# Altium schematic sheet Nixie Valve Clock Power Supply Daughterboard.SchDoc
size A4; SheetNumber: 1; SheetTotal: 3
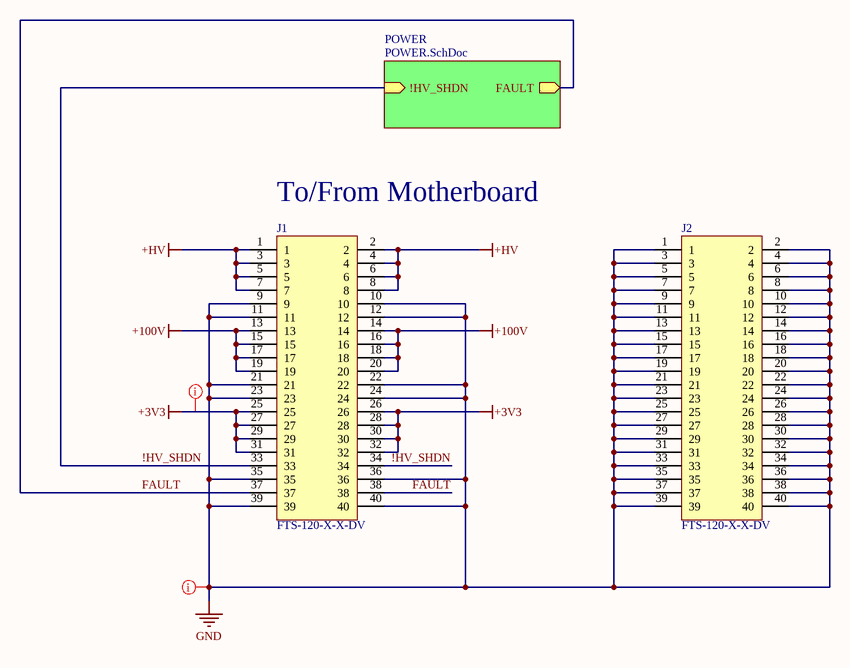
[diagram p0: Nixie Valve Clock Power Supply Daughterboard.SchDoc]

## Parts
?  (no value)
J1  FTS-120-X-X-DV  [SAMTEC_FTS-120-X-X-DV]
J2  FTS-120-X-X-DV  [SAMTEC_FTS-120-X-X-DV]

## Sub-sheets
POWER = POWER.SchDoc: !HV_SHDN (in), FAULT (out)

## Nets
+3V3: J1.25 J1.26 J1.27 J1.28 J1.29 J1.30 J1.31 J1.32
+100V: J1.13 J1.14 J1.15 J1.16 J1.17 J1.18 J1.19 J1.20
+HV: J1.1 J1.2 J1.3 J1.4 J1.5 J1.6 J1.7 J1.8
GND: J1.9 J1.10 J1.11 J1.12 J1.21 J1.22 J1.23 J1.24 J1.35 J1.36 J1.39 J1.40 J2.1 J2.2 J2.3 J2.4 J2.5 J2.6 J2.7 J2.8 J2.9 J2.10 J2.11 J2.12 J2.13 J2.14 J2.15 J2.16 J2.17 J2.18 J2.19 J2.20 J2.21 J2.22 J2.23 J2.24 J2.25 J2.26 J2.27 J2.28 J2.29 J2.30 J2.31 J2.32 J2.33 J2.34 J2.35 J2.36 J2.37 J2.38 J2.39 J2.40
!HV_SHDN: J1.33 J1.34 ; sheet POWER/!HV_SHDN
FAULT: J1.37 J1.38 ; sheet POWER/FAULT

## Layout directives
net class POWER: +3V3, GND

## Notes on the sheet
- (near J1) To/From Motherboard

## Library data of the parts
? = CMP-00003-4: The KETS Schematic Sheet Title Block
J1 J2 = CMP-002-00205-3: Pin Header, Board-to-Board, 1.27 mm, 2 Rows, 40 Contacts, Surface Mount, FTS Series; Manufacturer Lifecycle Status: PRODUCTION; Gender: Male; MP: FTS-120-02-L-DV; MF: Samtec; Current Rating: 1.75A; Pitch: 1.27mm; Number of Contacts: 40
